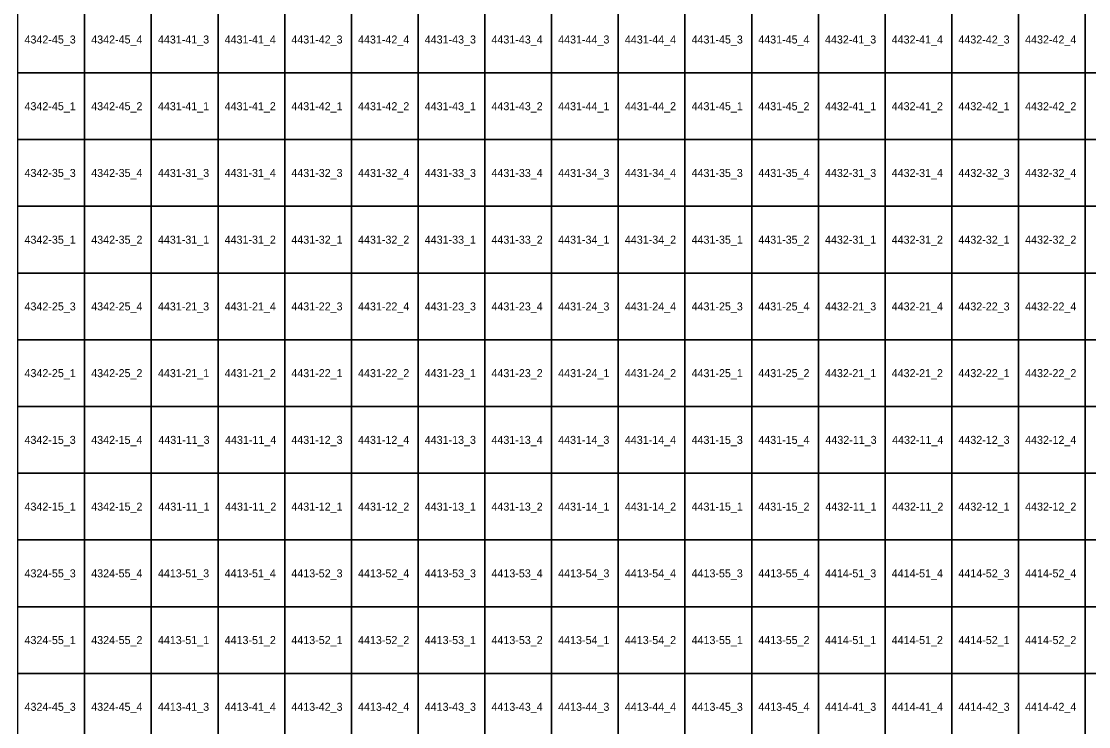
# Model space of a CAD drawing. Extents: x 312500 to 765000, y 172500 to 440000.
# Drawn here: x 595129 to 635129, y 343007 to 369429 of the extents above; entities that cross this region are included whole.
import ezdxf

# ---------------------------------------------------------------- set-up
doc = ezdxf.new("R2010")
doc.units = 0
doc.layers.add('Topo5_ramis_TKS2025', color=7, linetype='Continuous')
doc.layers.add('Topo5_ramis_TKS2025_Nr', color=7, linetype='Continuous')

msp = doc.modelspace()

# ---------------------------------------------------------------- linework, layer by layer
at = {"layer": 'Topo5_ramis_TKS2025'}
for points in [[(595000, 367500), (595000, 370000), (597500, 370000), (597500, 367500), (595000, 367500)], [(597500, 367500), (597500, 370000), (600000, 370000), (600000, 367500), (597500, 367500)], [(600000, 367500), (600000, 370000), (602500, 370000), (602500, 367500), (600000, 367500)], [(602500, 367500), (602500, 370000), (605000, 370000), (605000, 367500), (602500, 367500)], [(605000, 367500), (605000, 370000), (607500, 370000), (607500, 367500), (605000, 367500)], [(607500, 367500), (607500, 370000), (610000, 370000), (610000, 367500), (607500, 367500)], [(610000, 367500), (610000, 370000), (612500, 370000), (612500, 367500), (610000, 367500)], [(612500, 367500), (612500, 370000), (615000, 370000), (615000, 367500), (612500, 367500)], [(615000, 367500), (615000, 370000), (617500, 370000), (617500, 367500), (615000, 367500)], [(617500, 367500), (617500, 370000), (620000, 370000), (620000, 367500), (617500, 367500)], [(620000, 367500), (620000, 370000), (622500, 370000), (622500, 367500), (620000, 367500)], [(622500, 367500), (622500, 370000), (625000, 370000), (625000, 367500), (622500, 367500)], [(625000, 367500), (625000, 370000), (627500, 370000), (627500, 367500), (625000, 367500)], [(627500, 367500), (627500, 370000), (630000, 370000), (630000, 367500), (627500, 367500)], [(630000, 367500), (630000, 370000), (632500, 370000), (632500, 367500), (630000, 367500)], [(632500, 367500), (632500, 370000), (635000, 370000), (635000, 367500), (632500, 367500)], [(635000, 367500), (635000, 370000), (637500, 370000), (637500, 367500), (635000, 367500)], [(595000, 365000), (595000, 367500), (597500, 367500), (597500, 365000), (595000, 365000)], [(597500, 365000), (597500, 367500), (600000, 367500), (600000, 365000), (597500, 365000)], [(600000, 365000), (600000, 367500), (602500, 367500), (602500, 365000), (600000, 365000)], [(602500, 365000), (602500, 367500), (605000, 367500), (605000, 365000), (602500, 365000)], [(605000, 365000), (605000, 367500), (607500, 367500), (607500, 365000), (605000, 365000)], [(607500, 365000), (607500, 367500), (610000, 367500), (610000, 365000), (607500, 365000)], [(610000, 365000), (610000, 367500), (612500, 367500), (612500, 365000), (610000, 365000)], [(612500, 365000), (612500, 367500), (615000, 367500), (615000, 365000), (612500, 365000)], [(615000, 365000), (615000, 367500), (617500, 367500), (617500, 365000), (615000, 365000)], [(617500, 365000), (617500, 367500), (620000, 367500), (620000, 365000), (617500, 365000)], [(620000, 365000), (620000, 367500), (622500, 367500), (622500, 365000), (620000, 365000)], [(622500, 365000), (622500, 367500), (625000, 367500), (625000, 365000), (622500, 365000)], [(625000, 365000), (625000, 367500), (627500, 367500), (627500, 365000), (625000, 365000)], [(627500, 365000), (627500, 367500), (630000, 367500), (630000, 365000), (627500, 365000)], [(630000, 365000), (630000, 367500), (632500, 367500), (632500, 365000), (630000, 365000)], [(632500, 365000), (632500, 367500), (635000, 367500), (635000, 365000), (632500, 365000)], [(635000, 365000), (635000, 367500), (637500, 367500), (637500, 365000), (635000, 365000)], [(595000, 362500), (595000, 365000), (597500, 365000), (597500, 362500), (595000, 362500)], [(597500, 362500), (597500, 365000), (600000, 365000), (600000, 362500), (597500, 362500)], [(600000, 362500), (600000, 365000), (602500, 365000), (602500, 362500), (600000, 362500)], [(602500, 362500), (602500, 365000), (605000, 365000), (605000, 362500), (602500, 362500)], [(605000, 362500), (605000, 365000), (607500, 365000), (607500, 362500), (605000, 362500)], [(607500, 362500), (607500, 365000), (610000, 365000), (610000, 362500), (607500, 362500)], [(610000, 362500), (610000, 365000), (612500, 365000), (612500, 362500), (610000, 362500)], [(612500, 362500), (612500, 365000), (615000, 365000), (615000, 362500), (612500, 362500)], [(615000, 362500), (615000, 365000), (617500, 365000), (617500, 362500), (615000, 362500)], [(617500, 362500), (617500, 365000), (620000, 365000), (620000, 362500), (617500, 362500)], [(620000, 362500), (620000, 365000), (622500, 365000), (622500, 362500), (620000, 362500)], [(622500, 362500), (622500, 365000), (625000, 365000), (625000, 362500), (622500, 362500)], [(625000, 362500), (625000, 365000), (627500, 365000), (627500, 362500), (625000, 362500)], [(627500, 362500), (627500, 365000), (630000, 365000), (630000, 362500), (627500, 362500)], [(630000, 362500), (630000, 365000), (632500, 365000), (632500, 362500), (630000, 362500)], [(632500, 362500), (632500, 365000), (635000, 365000), (635000, 362500), (632500, 362500)], [(635000, 362500), (635000, 365000), (637500, 365000), (637500, 362500), (635000, 362500)], [(595000, 360000), (595000, 362500), (597500, 362500), (597500, 360000), (595000, 360000)], [(597500, 360000), (597500, 362500), (600000, 362500), (600000, 360000), (597500, 360000)], [(600000, 360000), (600000, 362500), (602500, 362500), (602500, 360000), (600000, 360000)], [(602500, 360000), (602500, 362500), (605000, 362500), (605000, 360000), (602500, 360000)], [(605000, 360000), (605000, 362500), (607500, 362500), (607500, 360000), (605000, 360000)], [(607500, 360000), (607500, 362500), (610000, 362500), (610000, 360000), (607500, 360000)], [(610000, 360000), (610000, 362500), (612500, 362500), (612500, 360000), (610000, 360000)], [(612500, 360000), (612500, 362500), (615000, 362500), (615000, 360000), (612500, 360000)], [(615000, 360000), (615000, 362500), (617500, 362500), (617500, 360000), (615000, 360000)], [(617500, 360000), (617500, 362500), (620000, 362500), (620000, 360000), (617500, 360000)], [(620000, 360000), (620000, 362500), (622500, 362500), (622500, 360000), (620000, 360000)], [(622500, 360000), (622500, 362500), (625000, 362500), (625000, 360000), (622500, 360000)], [(625000, 360000), (625000, 362500), (627500, 362500), (627500, 360000), (625000, 360000)], [(627500, 360000), (627500, 362500), (630000, 362500), (630000, 360000), (627500, 360000)], [(630000, 360000), (630000, 362500), (632500, 362500), (632500, 360000), (630000, 360000)], [(632500, 360000), (632500, 362500), (635000, 362500), (635000, 360000), (632500, 360000)], [(635000, 360000), (635000, 362500), (637500, 362500), (637500, 360000), (635000, 360000)], [(595000, 357500), (595000, 360000), (597500, 360000), (597500, 357500), (595000, 357500)], [(597500, 357500), (597500, 360000), (600000, 360000), (600000, 357500), (597500, 357500)], [(600000, 357500), (600000, 360000), (602500, 360000), (602500, 357500), (600000, 357500)], [(602500, 357500), (602500, 360000), (605000, 360000), (605000, 357500), (602500, 357500)], [(605000, 357500), (605000, 360000), (607500, 360000), (607500, 357500), (605000, 357500)], [(607500, 357500), (607500, 360000), (610000, 360000), (610000, 357500), (607500, 357500)], [(610000, 357500), (610000, 360000), (612500, 360000), (612500, 357500), (610000, 357500)], [(612500, 357500), (612500, 360000), (615000, 360000), (615000, 357500), (612500, 357500)], [(615000, 357500), (615000, 360000), (617500, 360000), (617500, 357500), (615000, 357500)], [(617500, 357500), (617500, 360000), (620000, 360000), (620000, 357500), (617500, 357500)], [(620000, 357500), (620000, 360000), (622500, 360000), (622500, 357500), (620000, 357500)], [(622500, 357500), (622500, 360000), (625000, 360000), (625000, 357500), (622500, 357500)], [(625000, 357500), (625000, 360000), (627500, 360000), (627500, 357500), (625000, 357500)], [(627500, 357500), (627500, 360000), (630000, 360000), (630000, 357500), (627500, 357500)], [(630000, 357500), (630000, 360000), (632500, 360000), (632500, 357500), (630000, 357500)], [(632500, 357500), (632500, 360000), (635000, 360000), (635000, 357500), (632500, 357500)], [(635000, 357500), (635000, 360000), (637500, 360000), (637500, 357500), (635000, 357500)], [(595000, 355000), (595000, 357500), (597500, 357500), (597500, 355000), (595000, 355000)], [(597500, 355000), (597500, 357500), (600000, 357500), (600000, 355000), (597500, 355000)], [(600000, 355000), (600000, 357500), (602500, 357500), (602500, 355000), (600000, 355000)], [(602500, 355000), (602500, 357500), (605000, 357500), (605000, 355000), (602500, 355000)], [(605000, 355000), (605000, 357500), (607500, 357500), (607500, 355000), (605000, 355000)], [(607500, 355000), (607500, 357500), (610000, 357500), (610000, 355000), (607500, 355000)], [(610000, 355000), (610000, 357500), (612500, 357500), (612500, 355000), (610000, 355000)], [(612500, 355000), (612500, 357500), (615000, 357500), (615000, 355000), (612500, 355000)], [(615000, 355000), (615000, 357500), (617500, 357500), (617500, 355000), (615000, 355000)], [(617500, 355000), (617500, 357500), (620000, 357500), (620000, 355000), (617500, 355000)], [(620000, 355000), (620000, 357500), (622500, 357500), (622500, 355000), (620000, 355000)], [(622500, 355000), (622500, 357500), (625000, 357500), (625000, 355000), (622500, 355000)], [(625000, 355000), (625000, 357500), (627500, 357500), (627500, 355000), (625000, 355000)], [(627500, 355000), (627500, 357500), (630000, 357500), (630000, 355000), (627500, 355000)], [(630000, 355000), (630000, 357500), (632500, 357500), (632500, 355000), (630000, 355000)], [(632500, 355000), (632500, 357500), (635000, 357500), (635000, 355000), (632500, 355000)], [(635000, 355000), (635000, 357500), (637500, 357500), (637500, 355000), (635000, 355000)], [(595000, 352500), (595000, 355000), (597500, 355000), (597500, 352500), (595000, 352500)], [(597500, 352500), (597500, 355000), (600000, 355000), (600000, 352500), (597500, 352500)], [(600000, 352500), (600000, 355000), (602500, 355000), (602500, 352500), (600000, 352500)], [(602500, 352500), (602500, 355000), (605000, 355000), (605000, 352500), (602500, 352500)], [(605000, 352500), (605000, 355000), (607500, 355000), (607500, 352500), (605000, 352500)], [(607500, 352500), (607500, 355000), (610000, 355000), (610000, 352500), (607500, 352500)], [(610000, 352500), (610000, 355000), (612500, 355000), (612500, 352500), (610000, 352500)], [(612500, 352500), (612500, 355000), (615000, 355000), (615000, 352500), (612500, 352500)], [(615000, 352500), (615000, 355000), (617500, 355000), (617500, 352500), (615000, 352500)], [(617500, 352500), (617500, 355000), (620000, 355000), (620000, 352500), (617500, 352500)], [(620000, 352500), (620000, 355000), (622500, 355000), (622500, 352500), (620000, 352500)], [(622500, 352500), (622500, 355000), (625000, 355000), (625000, 352500), (622500, 352500)], [(625000, 352500), (625000, 355000), (627500, 355000), (627500, 352500), (625000, 352500)], [(627500, 352500), (627500, 355000), (630000, 355000), (630000, 352500), (627500, 352500)], [(630000, 352500), (630000, 355000), (632500, 355000), (632500, 352500), (630000, 352500)], [(632500, 352500), (632500, 355000), (635000, 355000), (635000, 352500), (632500, 352500)], [(635000, 352500), (635000, 355000), (637500, 355000), (637500, 352500), (635000, 352500)], [(595000, 350000), (595000, 352500), (597500, 352500), (597500, 350000), (595000, 350000)], [(597500, 350000), (597500, 352500), (600000, 352500), (600000, 350000), (597500, 350000)], [(600000, 350000), (600000, 352500), (602500, 352500), (602500, 350000), (600000, 350000)], [(602500, 350000), (602500, 352500), (605000, 352500), (605000, 350000), (602500, 350000)], [(605000, 350000), (605000, 352500), (607500, 352500), (607500, 350000), (605000, 350000)], [(607500, 350000), (607500, 352500), (610000, 352500), (610000, 350000), (607500, 350000)], [(610000, 350000), (610000, 352500), (612500, 352500), (612500, 350000), (610000, 350000)], [(612500, 350000), (612500, 352500), (615000, 352500), (615000, 350000), (612500, 350000)], [(615000, 350000), (615000, 352500), (617500, 352500), (617500, 350000), (615000, 350000)], [(617500, 350000), (617500, 352500), (620000, 352500), (620000, 350000), (617500, 350000)], [(620000, 350000), (620000, 352500), (622500, 352500), (622500, 350000), (620000, 350000)], [(622500, 350000), (622500, 352500), (625000, 352500), (625000, 350000), (622500, 350000)], [(625000, 350000), (625000, 352500), (627500, 352500), (627500, 350000), (625000, 350000)], [(627500, 350000), (627500, 352500), (630000, 352500), (630000, 350000), (627500, 350000)], [(630000, 350000), (630000, 352500), (632500, 352500), (632500, 350000), (630000, 350000)], [(632500, 350000), (632500, 352500), (635000, 352500), (635000, 350000), (632500, 350000)], [(635000, 350000), (635000, 352500), (637500, 352500), (637500, 350000), (635000, 350000)], [(595000, 347500), (595000, 350000), (597500, 350000), (597500, 347500), (595000, 347500)], [(597500, 347500), (597500, 350000), (600000, 350000), (600000, 347500), (597500, 347500)], [(600000, 347500), (600000, 350000), (602500, 350000), (602500, 347500), (600000, 347500)], [(602500, 347500), (602500, 350000), (605000, 350000), (605000, 347500), (602500, 347500)], [(605000, 347500), (605000, 350000), (607500, 350000), (607500, 347500), (605000, 347500)], [(607500, 347500), (607500, 350000), (610000, 350000), (610000, 347500), (607500, 347500)], [(610000, 347500), (610000, 350000), (612500, 350000), (612500, 347500), (610000, 347500)], [(612500, 347500), (612500, 350000), (615000, 350000), (615000, 347500), (612500, 347500)], [(615000, 347500), (615000, 350000), (617500, 350000), (617500, 347500), (615000, 347500)], [(617500, 347500), (617500, 350000), (620000, 350000), (620000, 347500), (617500, 347500)], [(620000, 347500), (620000, 350000), (622500, 350000), (622500, 347500), (620000, 347500)], [(622500, 347500), (622500, 350000), (625000, 350000), (625000, 347500), (622500, 347500)], [(625000, 347500), (625000, 350000), (627500, 350000), (627500, 347500), (625000, 347500)], [(627500, 347500), (627500, 350000), (630000, 350000), (630000, 347500), (627500, 347500)], [(630000, 347500), (630000, 350000), (632500, 350000), (632500, 347500), (630000, 347500)], [(632500, 347500), (632500, 350000), (635000, 350000), (635000, 347500), (632500, 347500)], [(635000, 347500), (635000, 350000), (637500, 350000), (637500, 347500), (635000, 347500)], [(595000, 345000), (595000, 347500), (597500, 347500), (597500, 345000), (595000, 345000)], [(597500, 345000), (597500, 347500), (600000, 347500), (600000, 345000), (597500, 345000)], [(600000, 345000), (600000, 347500), (602500, 347500), (602500, 345000), (600000, 345000)], [(602500, 345000), (602500, 347500), (605000, 347500), (605000, 345000), (602500, 345000)], [(605000, 345000), (605000, 347500), (607500, 347500), (607500, 345000), (605000, 345000)], [(607500, 345000), (607500, 347500), (610000, 347500), (610000, 345000), (607500, 345000)], [(610000, 345000), (610000, 347500), (612500, 347500), (612500, 345000), (610000, 345000)], [(612500, 345000), (612500, 347500), (615000, 347500), (615000, 345000), (612500, 345000)], [(615000, 345000), (615000, 347500), (617500, 347500), (617500, 345000), (615000, 345000)], [(617500, 345000), (617500, 347500), (620000, 347500), (620000, 345000), (617500, 345000)], [(620000, 345000), (620000, 347500), (622500, 347500), (622500, 345000), (620000, 345000)], [(622500, 345000), (622500, 347500), (625000, 347500), (625000, 345000), (622500, 345000)], [(625000, 345000), (625000, 347500), (627500, 347500), (627500, 345000), (625000, 345000)], [(627500, 345000), (627500, 347500), (630000, 347500), (630000, 345000), (627500, 345000)], [(630000, 345000), (630000, 347500), (632500, 347500), (632500, 345000), (630000, 345000)], [(632500, 345000), (632500, 347500), (635000, 347500), (635000, 345000), (632500, 345000)], [(635000, 345000), (635000, 347500), (637500, 347500), (637500, 345000), (635000, 345000)], [(595000, 342500), (595000, 345000), (597500, 345000), (597500, 342500), (595000, 342500)], [(597500, 342500), (597500, 345000), (600000, 345000), (600000, 342500), (597500, 342500)], [(600000, 342500), (600000, 345000), (602500, 345000), (602500, 342500), (600000, 342500)], [(602500, 342500), (602500, 345000), (605000, 345000), (605000, 342500), (602500, 342500)], [(605000, 342500), (605000, 345000), (607500, 345000), (607500, 342500), (605000, 342500)], [(607500, 342500), (607500, 345000), (610000, 345000), (610000, 342500), (607500, 342500)], [(610000, 342500), (610000, 345000), (612500, 345000), (612500, 342500), (610000, 342500)], [(612500, 342500), (612500, 345000), (615000, 345000), (615000, 342500), (612500, 342500)], [(615000, 342500), (615000, 345000), (617500, 345000), (617500, 342500), (615000, 342500)], [(617500, 342500), (617500, 345000), (620000, 345000), (620000, 342500), (617500, 342500)], [(620000, 342500), (620000, 345000), (622500, 345000), (622500, 342500), (620000, 342500)], [(622500, 342500), (622500, 345000), (625000, 345000), (625000, 342500), (622500, 342500)], [(625000, 342500), (625000, 345000), (627500, 345000), (627500, 342500), (625000, 342500)], [(627500, 342500), (627500, 345000), (630000, 345000), (630000, 342500), (627500, 342500)], [(630000, 342500), (630000, 345000), (632500, 345000), (632500, 342500), (630000, 342500)], [(632500, 342500), (632500, 345000), (635000, 345000), (635000, 342500), (632500, 342500)], [(635000, 342500), (635000, 345000), (637500, 345000), (637500, 342500), (635000, 342500)]]:
    msp.add_lwpolyline(points, dxfattribs=at)

# ---------------------------------------------------------------- texts
at = {"layer": 'Topo5_ramis_TKS2025_Nr'}
for s, p in [('4342-45_3', (595248, 368600)), ('4342-45_4', (597748, 368600)), ('4431-41_3', (600248, 368600)), ('4431-41_4', (602748, 368600)), ('4431-42_3', (605248, 368600)), ('4431-42_4', (607748, 368600)), ('4431-43_3', (610248, 368600)), ('4431-43_4', (612748, 368600)), ('4431-44_3', (615248, 368600)), ('4431-44_4', (617748, 368600)), ('4431-45_3', (620248, 368600)), ('4431-45_4', (622748, 368600)), ('4432-41_3', (625248, 368600)), ('4432-41_4', (627748, 368600)), ('4432-42_3', (630248, 368600)), ('4432-42_4', (632748, 368600)), ('4342-45_1', (595248, 366100)), ('4342-45_2', (597748, 366100)), ('4431-41_1', (600248, 366100)), ('4431-41_2', (602748, 366100)), ('4431-42_1', (605248, 366100)), ('4431-42_2', (607748, 366100)), ('4431-43_1', (610248, 366100)), ('4431-43_2', (612748, 366100)), ('4431-44_1', (615248, 366100)), ('4431-44_2', (617748, 366100)), ('4431-45_1', (620248, 366100)), ('4431-45_2', (622748, 366100)), ('4432-41_1', (625248, 366100)), ('4432-41_2', (627748, 366100)), ('4432-42_1', (630248, 366100)), ('4432-42_2', (632748, 366100)), ('4342-35_3', (595248, 363600)), ('4342-35_4', (597748, 363600)), ('4431-31_3', (600248, 363600)), ('4431-31_4', (602748, 363600)), ('4431-32_3', (605248, 363600)), ('4431-32_4', (607748, 363600)), ('4431-33_3', (610248, 363600)), ('4431-33_4', (612748, 363600)), ('4431-34_3', (615248, 363600)), ('4431-34_4', (617748, 363600)), ('4431-35_3', (620248, 363600)), ('4431-35_4', (622748, 363600)), ('4432-31_3', (625248, 363600)), ('4432-31_4', (627748, 363600)), ('4432-32_3', (630248, 363600)), ('4432-32_4', (632748, 363600)), ('4342-35_1', (595248, 361100)), ('4342-35_2', (597748, 361100)), ('4431-31_1', (600248, 361100)), ('4431-31_2', (602748, 361100)), ('4431-32_1', (605248, 361100)), ('4431-32_2', (607748, 361100)), ('4431-33_1', (610248, 361100)), ('4431-33_2', (612748, 361100)), ('4431-34_1', (615248, 361100)), ('4431-34_2', (617748, 361100)), ('4431-35_1', (620248, 361100)), ('4431-35_2', (622748, 361100)), ('4432-31_1', (625248, 361100)), ('4432-31_2', (627748, 361100)), ('4432-32_1', (630248, 361100)), ('4432-32_2', (632748, 361100)), ('4342-25_3', (595248, 358600)), ('4342-25_4', (597748, 358600)), ('4431-21_3', (600248, 358600)), ('4431-21_4', (602748, 358600)), ('4431-22_3', (605248, 358600)), ('4431-22_4', (607748, 358600)), ('4431-23_3', (610248, 358600)), ('4431-23_4', (612748, 358600)), ('4431-24_3', (615248, 358600)), ('4431-24_4', (617748, 358600)), ('4431-25_3', (620248, 358600)), ('4431-25_4', (622748, 358600)), ('4432-21_3', (625248, 358600)), ('4432-21_4', (627748, 358600)), ('4432-22_3', (630248, 358600)), ('4432-22_4', (632748, 358600)), ('4342-25_1', (595248, 356100)), ('4342-25_2', (597748, 356100)), ('4431-21_1', (600248, 356100)), ('4431-21_2', (602748, 356100)), ('4431-22_1', (605248, 356100)), ('4431-22_2', (607748, 356100)), ('4431-23_1', (610248, 356100)), ('4431-23_2', (612748, 356100)), ('4431-24_1', (615248, 356100)), ('4431-24_2', (617748, 356100)), ('4431-25_1', (620248, 356100)), ('4431-25_2', (622748, 356100)), ('4432-21_1', (625248, 356100)), ('4432-21_2', (627748, 356100)), ('4432-22_1', (630248, 356100)), ('4432-22_2', (632748, 356100)), ('4342-15_3', (595248, 353600)), ('4342-15_4', (597748, 353600)), ('4431-11_3', (600264, 353600)), ('4431-11_4', (602764, 353600)), ('4431-12_3', (605248, 353600)), ('4431-12_4', (607748, 353600)), ('4431-13_3', (610248, 353600)), ('4431-13_4', (612748, 353600)), ('4431-14_3', (615248, 353600)), ('4431-14_4', (617748, 353600)), ('4431-15_3', (620248, 353600)), ('4431-15_4', (622748, 353600)), ('4432-11_3', (625264, 353600)), ('4432-11_4', (627764, 353600)), ('4432-12_3', (630248, 353600)), ('4432-12_4', (632748, 353600)), ('4342-15_1', (595248, 351100)), ('4342-15_2', (597748, 351100)), ('4431-11_1', (600264, 351100)), ('4431-11_2', (602764, 351100)), ('4431-12_1', (605248, 351100)), ('4431-12_2', (607748, 351100)), ('4431-13_1', (610248, 351100)), ('4431-13_2', (612748, 351100)), ('4431-14_1', (615248, 351100)), ('4431-14_2', (617748, 351100)), ('4431-15_1', (620248, 351100)), ('4431-15_2', (622748, 351100)), ('4432-11_1', (625264, 351100)), ('4432-11_2', (627764, 351100)), ('4432-12_1', (630248, 351100)), ('4432-12_2', (632748, 351100)), ('4324-55_3', (595248, 348600)), ('4324-55_4', (597748, 348600)), ('4413-51_3', (600248, 348600)), ('4413-51_4', (602748, 348600)), ('4413-52_3', (605248, 348600)), ('4413-52_4', (607748, 348600)), ('4413-53_3', (610248, 348600)), ('4413-53_4', (612748, 348600)), ('4413-54_3', (615248, 348600)), ('4413-54_4', (617748, 348600)), ('4413-55_3', (620248, 348600)), ('4413-55_4', (622748, 348600)), ('4414-51_3', (625248, 348600)), ('4414-51_4', (627748, 348600)), ('4414-52_3', (630248, 348600)), ('4414-52_4', (632748, 348600)), ('4324-55_1', (595248, 346100)), ('4324-55_2', (597748, 346100)), ('4413-51_1', (600248, 346100)), ('4413-51_2', (602748, 346100)), ('4413-52_1', (605248, 346100)), ('4413-52_2', (607748, 346100)), ('4413-53_1', (610248, 346100)), ('4413-53_2', (612748, 346100)), ('4413-54_1', (615248, 346100)), ('4413-54_2', (617748, 346100)), ('4413-55_1', (620248, 346100)), ('4413-55_2', (622748, 346100)), ('4414-51_1', (625248, 346100)), ('4414-51_2', (627748, 346100)), ('4414-52_1', (630248, 346100)), ('4414-52_2', (632748, 346100)), ('4324-45_3', (595248, 343600)), ('4324-45_4', (597748, 343600)), ('4413-41_3', (600248, 343600)), ('4413-41_4', (602748, 343600)), ('4413-42_3', (605248, 343600)), ('4413-42_4', (607748, 343600)), ('4413-43_3', (610248, 343600)), ('4413-43_4', (612748, 343600)), ('4413-44_3', (615248, 343600)), ('4413-44_4', (617748, 343600)), ('4413-45_3', (620248, 343600)), ('4413-45_4', (622748, 343600)), ('4414-41_3', (625248, 343600)), ('4414-41_4', (627748, 343600)), ('4414-42_3', (630248, 343600)), ('4414-42_4', (632748, 343600))]:
    msp.add_text(s, height=300, dxfattribs=at).set_placement(p)

doc.saveas('drawing.dxf')
